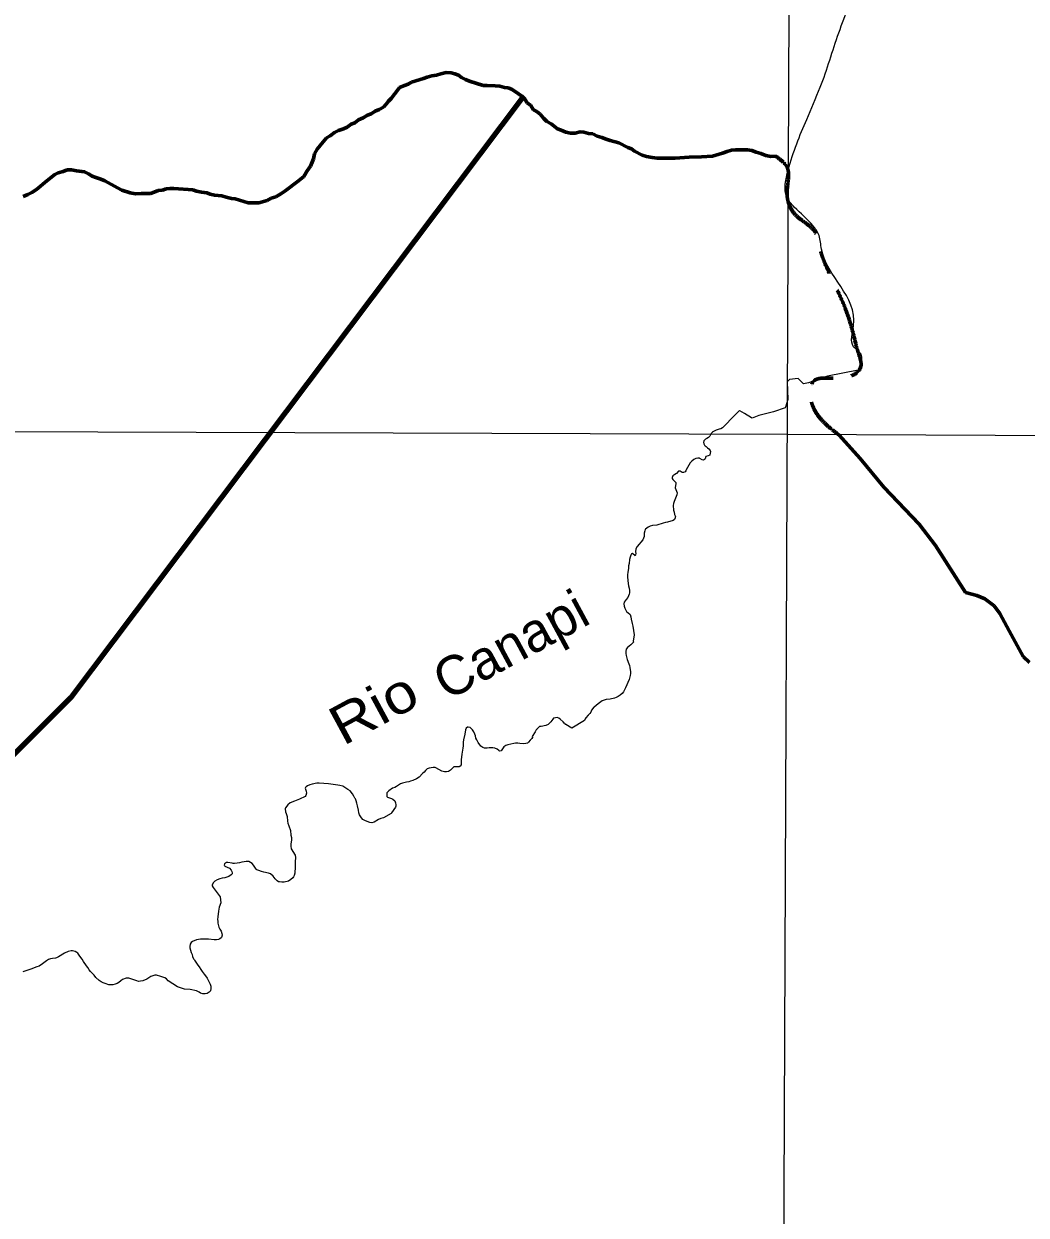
# Model space of a CAD drawing. Extents: x 553962 to 842807, y 8883888 to 9032388.
# Drawn here: x 655119 to 667950, y 8994810 to 9010061 of the extents above; entities that cross this region are included whole.
import ezdxf
from ezdxf.enums import TextEntityAlignment as Align

# ---------------------------------------------------------------- set-up
doc = ezdxf.new("R2010")
doc.units = 0
doc.header["$LTSCALE"] = 200
doc.linetypes.add('LONG_DASH_SHORT_DASH', pattern=[9.9, 6, -1.2, 1.5, -1.2])
for name, color, linetype, lineweight in [('1', 7, 'Continuous', 13), ('24', 7, 'Continuous', 25), ('7', 7, 'LONG_DASH_SHORT_DASH', 60), ('9', 7, 'Continuous', 90)]:
    doc.layers.add(name, color=color, linetype=linetype, lineweight=lineweight)
doc.layers.add('49', color=7, linetype='Continuous')

msp = doc.modelspace()

# ---------------------------------------------------------------- linework, layer by layer
at = {"layer": '1'}
for points in [[(664968.2, 9023436.8), (664657.1, 8949509), (664397.1, 8890880.2)], [(565303.2, 9005146.6), (664889.8, 9004806.7), (719872.1, 9004543.9), (790635.8, 9004109)]]:
    msp.add_lwpolyline(points, dxfattribs=at)
at = {"layer": '24'}
for points in [[(665798.1, 9005626.6), (665405.1, 9005550.8), (665165.6, 9005466.5), (665101.5, 9005450.6), (665032.2, 9005519.9), (664921.3, 9005506.1), (664888.7, 9005478.8)], [(664888.7, 9005478.8), (664900.1, 9005251.2), (664869.8, 9005153.3), (664865.4, 9005145.8), (664717.4, 9005095.4), (664528.5, 9005045), (664441.2, 9005012.7), (664432.8, 9005015.5), (664343.5, 9005072.6), (664286.2, 9005107.2), (664280.8, 9005109), (664271.5, 9005101.5), (664208.7, 9005038.3), (664080.1, 9004905.7)], [(664080.1, 9004905.7), (664063.5, 9004888.7), (664040.8, 9004876.6), (664021.9, 9004870), (663980.2, 9004861.2), (663946.3, 9004843.8), (663931.6, 9004832.2), (663929.7, 9004827.5), (663925.3, 9004825.6), (663922.8, 9004820.1), (663917.9, 9004815.5), (663910.5, 9004801.1), (663899, 9004783.8), (663883.9, 9004765), (663863.8, 9004751.9), (663845.5, 9004742.3), (663830.7, 9004729.4), (663824.8, 9004721.3), (663819.7, 9004702.6), (663823.3, 9004691.5), (663824.1, 9004683.3), (663832.8, 9004668.7), (663842.4, 9004656.8), (663854.1, 9004648.1), (663869.6, 9004633.8), (663887.6, 9004620.7), (663907, 9004598.9), (663907, 9004598.9), (663910.9, 9004584.5), (663902.4, 9004543.4), (663900.7, 9004539.3), (663881.2, 9004529), (663848.8, 9004520.2), (663839.5, 9004493.6), (663833.8, 9004483.1), (663820.7, 9004477), (663803.2, 9004478.8), (663774.4, 9004497.4), (663769.2, 9004499), (663746.7, 9004499.8), (663720.6, 9004496.7), (663695.8, 9004484.7), (663668.4, 9004461.3), (663648.1, 9004440.9), (663597.4, 9004352.2)], [(663597.4, 9004352.2), (663591.9, 9004338.7), (663585.2, 9004327.5), (663562, 9004318.3), (663545.8, 9004318.1), (663534.7, 9004324.6), (663525, 9004333.9), (663497.8, 9004335.9), (663473.3, 9004304.2), (663451.5, 9004291.8), (663425.3, 9004274.1), (663419.2, 9004251.7), (663419.6, 9004240.3), (663428.8, 9004227), (663461.2, 9004195.3), (663463.7, 9004190.3), (663466.9, 9004175.9), (663457.9, 9004121.1), (663483.9, 9004058.1), (663479.5, 9004030.4), (663444.7, 9003947.7), (663436.1, 9003919.8), (663430, 9003892.9), (663436.2, 9003836.4), (663444.6, 9003808.5), (663450.1, 9003780.8), (663459.3, 9003752.9), (663454.4, 9003726), (663450.1, 9003716.1), (663431.3, 9003702.2), (663360.9, 9003681.5), (663332.3, 9003676.8), (663305.3, 9003670.6), (663276.6, 9003659.9), (663248.8, 9003653.3), (663221, 9003644.9), (663165.3, 9003637.2), (663137.5, 9003629.7), (663109.8, 9003617.9), (663077.1, 9003593.6), (663073.8, 9003588.8), (663066.6, 9003572.2), (663061.7, 9003539.8), (663061.5, 9003511.9), (663059.4, 9003496.8), (663040.9, 9003457.1), (662971.2, 9003371.5), (662951.9, 9003338.4), (662948.3, 9003299.8), (662954, 9003282), (662947.1, 9003264.8), (662944, 9003251.6), (662942.9, 9003251.1), (662911.9, 9003278.6), (662899.6, 9003277.8), (662888.3, 9003260.5), (662879.6, 9003232.8), (662873.2, 9003204.9), (662866.8, 9003150.2), (662861.5, 9003121.4), (662858.9, 9003091.8), (662849.7, 9003038), (662846.5, 9003010.2), (662846.6, 9002979.2), (662855.1, 9002895.8), (662859.3, 9002866.8), (662868.7, 9002836.8), (662871.9, 9002808.7), (662871, 9002777.8), (662869.2, 9002761.2), (662849.1, 9002718.3), (662831.4, 9002691.2), (662805.1, 9002656.3), (662801.6, 9002634.7), (662804.8, 9002607.8), (662812, 9002578.7), (662832, 9002539.4), (662877.8, 9002502.9), (662881.5, 9002497.6), (662889.1, 9002470.7), (662893.7, 9002439.9), (662905.9, 9002382.7), (662915.2, 9002349), (662932.3, 9002238.2)], [(662932.3, 9002238.2), (662930.4, 9002232.8), (662918.7, 9002162.2), (662919.1, 9002158.4), (662924.3, 9002149.5), (662924.7, 9002146.9), (662910.5, 9002130.5), (662890.5, 9002112.2), (662844.9, 9002076.1), (662830.6, 9002055.4), (662824.1, 9002025.5), (662826.1, 9001999.9), (662830.2, 9001975), (662842.8, 9001924.6), (662865.6, 9001868.5), (662873.1, 9001845.7), (662878.6, 9001819.2), (662886, 9001766.9), (662885.8, 9001743), (662880.8, 9001718.2), (662866.3, 9001665.2), (662823, 9001561.5), (662795.5, 9001511.2), (662776.8, 9001488.3), (662751.1, 9001464.8), (662727, 9001447.9), (662703, 9001435.9), (662679.1, 9001427.9), (662625.9, 9001415.6), (662573.7, 9001409.9), (662524, 9001394.2), (662471, 9001354.5)], [(662471, 9001354.5), (662418, 9001314.7), (662413.9, 9001313.1), (662387.4, 9001275.2), (662375.4, 9001250.8), (662363.1, 9001233.2), (662344.9, 9001211.6), (662312, 9001177.4), (662303.6, 9001164.2), (662297.6, 9001142.3), (662132.9, 9001044.6), (662055.9, 9001090.7), (662051.5, 9001092.1), (662048.6, 9001095.2), (662046.8, 9001099.7), (662037.3, 9001108.4), (662022.2, 9001125.4), (661983.8, 9001159.7), (661966.6, 9001172.4), (661944.8, 9001178.8), (661926.5, 9001177.5), (661909.8, 9001173.8), (661901.4, 9001170.2), (661890.7, 9001159.3), (661864.8, 9001124.2), (661848.9, 9001108.4), (661829.4, 9001092.8), (661799.7, 9001079.5), (661781.2, 9001073.3), (661761.2, 9001070.8), (661742.7, 9001066.8), (661725.3, 9001066.6), (661721.3, 9001065.5), (661706.2, 9001054.2), (661685.2, 9001030.2), (661683.4, 9001024.9), (661678.4, 9001021.4), (661666.2, 9000995.9)], [(661666.2, 9000995.9), (661666, 9000995.8), (661628.2, 9000939.1), (661629.1, 9000923.3), (661621.8, 9000911.6), (661602.7, 9000889), (661580.6, 9000865.8), (661565.2, 9000853.8), (661545, 9000847.3), (661519.3, 9000842.1), (661468.8, 9000846.1), (661442.2, 9000850.3), (661414.8, 9000850.2), (661390.9, 9000847.2), (661313.8, 9000829), (661288.2, 9000820.3), (661264.1, 9000805.4), (661227.5, 9000755.1), (661208, 9000751.3), (661198.2, 9000757.5), (661179.9, 9000776.4), (661150.3, 9000789.5), (661123.7, 9000793.6), (661075.9, 9000790.6), (661048.4, 9000786.4), (661015, 9000789.2), (660997, 9000798), (660969.6, 9000815.2), (660936.1, 9000861.2), (660916.9, 9000893.2), (660906.5, 9000918), (660902.7, 9000944.6), (660893.5, 9000969.5), (660880.3, 9000995.9), (660864.7, 9001020.9), (660846.7, 9001041.3), (660832.8, 9001051.1), (660807.4, 9001057.7), (660797.2, 9001057), (660783.2, 9001044), (660772.5, 9001021.6), (660765.5, 9000968.5), (660747.9, 9000894.1), (660744.4, 9000865.7), (660743.2, 9000816.2), (660736.9, 9000789.6), (660730.5, 9000739.1), (660724.1, 9000712.6), (660715.8, 9000638.2), (660717.6, 9000586.8), (660716.8, 9000576.4), (660703.4, 9000556.3), (660691.2, 9000550.9), (660651.6, 9000550.6), (660627.7, 9000547.6), (660617, 9000544), (660613.3, 9000541.4), (660580.1, 9000504.8), (660556, 9000490), (660529.6, 9000484.5), (660503.9, 9000484.7), (660470.1, 9000491.9), (660394.1, 9000535.8), (660385, 9000538.7), (660360.5, 9000540.9), (660309.2, 9000533.2), (660284.4, 9000522.9), (660273.5, 9000516.3)], [(660273.5, 9000516.3), (660260.7, 9000503.6), (660242.4, 9000482.3), (660221.6, 9000464.5), (660179.6, 9000416.4), (660146.5, 9000396.3), (660098.7, 9000374.4), (660070.2, 9000365.5), (660046.2, 9000355.7), (660017.1, 9000352.3), (659968.3, 9000340.1), (659941.1, 9000330.8), (659916.1, 9000316.3), (659891.5, 9000299.3), (659868.5, 9000285.3), (659840.5, 9000274.1), (659791.5, 9000243.5), (659791.5, 9000243.5), (659764.1, 9000216.7)], [(659764.1, 9000216.7), (659766.6, 9000170.3), (659768.2, 9000165.1), (659774.5, 9000160.6), (659826.5, 9000142.5), (659840.8, 9000136.1), (659866.7, 9000114.8), (659877.4, 9000088.4), (659881.6, 9000062.4), (659881.8, 9000044.3), (659878.7, 9000033.4), (659825.5, 8999960), (659819.5, 8999953.8), (659723.2, 8999895.5), (659688.5, 8999887.8), (659659.7, 8999873.4), (659605.7, 8999841.4), (659576.1, 8999832.9), (659549.3, 8999836.2), (659494.5, 8999857.3), (659459.2, 8999876.8), (659440.5, 8999897.3), (659416.9, 8999934), (659408.9, 8999962.1), (659405.4, 8999993), (659391.8, 9000051.2), (659380, 9000082), (659373.4, 9000111.9), (659363.4, 9000140), (659357.1, 9000148.2), (659344.6, 9000173.6), (659327.4, 9000201.8), (659297.2, 9000242.3), (659268.6, 9000258.6), (659204.1, 9000299.8), (659165.9, 9000310.6), (659139.1, 9000316.3), (659110, 9000320.5), (659049.2, 9000326.1), (659018.4, 9000330.3), (658960.2, 9000334.5), (658898.5, 9000340.9), (658868.6, 9000338.6), (658809.5, 9000327), (658781.4, 9000320), (658750.4, 9000304), (658731.6, 9000292.7), (658725, 9000283.2), (658721, 9000274), (658723.2, 9000264.3), (658735.2, 9000237.8), (658736.5, 9000212.6), (658728.3, 9000183.5), (658719.9, 9000170.5), (658646.8, 9000134.5), (658582.1, 9000107.9), (658527.1, 9000087.1), (658500.7, 9000063.1), (658466.8, 9000023.7), (658464.3, 9000011.6), (658467.1, 8999971.4), (658475.8, 8999953.7), (658488.4, 8999914.2), (658494.9, 8999855.1), (658500.1, 8999826), (658513.6, 8999793.3), (658531.7, 8999732.1), (658538.8, 8999675.3), (658544, 8999643.4), (658543.9, 8999614.5), (658535.6, 8999557.6), (658535.5, 8999531.6), (658542.9, 8999498.1), (658590.6, 8999417.1), (658596.3, 8999388.5), (658593.3, 8999333.7), (658594.3, 8999302.9), (658591.1, 8999245.1), (658587, 8999215.1), (658587.8, 8999186), (658581.9, 8999159.2), (658571.8, 8999140.2), (658561.5, 8999126.8), (658537.9, 8999105.5), (658506.5, 8999084.8), (658451.1, 8999073.9), (658421.2, 8999073.9), (658391.5, 8999076.1), (658380.9, 8999077.9), (658363.2, 8999087.9), (658334.8, 8999114.2), (658310.6, 8999148.7), (658278.5, 8999178.4), (658249.9, 8999187.4), (658191.8, 8999200), (658161.8, 8999208.5), (658129.2, 8999220.1), (658104, 8999230.8), (658091.6, 8999239.2), (658060.2, 8999290.2), (658040.3, 8999310.8)], [(658040.3, 8999310.8), (658040.3, 8999310.8), (658000, 8999337.8), (657966.4, 8999338.9), (657938.3, 8999334), (657908.4, 8999330.6), (657878.4, 8999322.2), (657850.3, 8999317.1), (657817.7, 8999313.6), (657800.3, 8999313.7), (657787.5, 8999316.9), (657729.5, 8999326.2), (657712.2, 8999324.4), (657688.6, 8999307.5), (657685.1, 8999292.1), (657687.3, 8999285.1), (657693, 8999275.8), (657753.2, 8999252.7), (657775, 8999226.5), (657782.3, 8999211.3), (657785.2, 8999193), (657784.6, 8999178.2), (657773.8, 8999165.3), (657744.9, 8999144), (657690.9, 8999127.6), (657660.1, 8999123), (657630.1, 8999116.6), (657595.5, 8999103.3), (657562.7, 8999084.1), (657548.4, 8999069.4), (657544.1, 8999063.3), (657530.6, 8999033.5), (657531.1, 8999026), (657541, 8999005.5), (657634.2, 8998884.3), (657639.8, 8998808), (657621.8, 8998753.6), (657615.4, 8998727.9), (657612.9, 8998701.4), (657601.6, 8998627.3), (657600.2, 8998596.8), (657601.2, 8998573), (657604.3, 8998548.1), (657616.1, 8998496.8), (657628.2, 8998469.8), (657644.2, 8998443.7), (657653.9, 8998417.1), (657657.6, 8998393.2), (657648.4, 8998365.3), (657644.6, 8998359), (657626.4, 8998346.5), (657609.5, 8998339.4), (657584.9, 8998335.4), (657557.6, 8998334.5), (657484.2, 8998341.6), (657456.7, 8998341.8), (657430.2, 8998343.8), (657405.3, 8998342.9), (657378.8, 8998343.7), (657329.2, 8998335.4), (657279.9, 8998312.1), (657261.7, 8998299.4), (657250.3, 8998279.6), (657242.8, 8998249.8), (657243.3, 8998231.8), (657260.7, 8998173.6), (657272.5, 8998147), (657279.3, 8998120.5), (657289.5, 8998090.3), (657298.5, 8998083.2), (657303.2, 8998074.5), (657330.3, 8998035.7), (657345, 8998010.8), (657364.6, 8997987.5), (657384, 8997954.4), (657403.7, 8997929), (657426.3, 8997895.3), (657445.7, 8997875.4), (657467.3, 8997843.1), (657480.4, 8997819), (657504, 8997765.2), (657512, 8997741.1), (657513.1, 8997712.8), (657507.4, 8997682.2), (657504.9, 8997678.3), (657489.8, 8997663.3), (657464.9, 8997646.8), (657439.6, 8997643), (657411, 8997643.7), (657379.6, 8997651.8), (657363.8, 8997663.7), (657331.7, 8997680.8), (657249.9, 8997700.5), (657175.3, 8997701)], [(657175.3, 8997701), (657175.1, 8997701), (657100.8, 8997730.4), (657087.9, 8997731.3), (656968.2, 8997810), (656946.1, 8997833.3), (656924.4, 8997848.9), (656898.9, 8997857.8), (656872.4, 8997864.6), (656819.7, 8997882.6), (656819.7, 8997882.6), (656795.3, 8997881.5), (656768.8, 8997874.8), (656744, 8997863.3), (656694.2, 8997832.3), (656641.2, 8997809), (656614.7, 8997804.5), (656588, 8997802.9), (656564.2, 8997808.9), (656487.1, 8997835.5), (656463.2, 8997842.5), (656437.6, 8997844), (656427.7, 8997843.1), (656383.6, 8997825.4), (656359.4, 8997809.3), (656333.6, 8997789), (656313.6, 8997776.8), (656288.8, 8997765.3), (656260.5, 8997757.4), (656235.8, 8997756.4), (656208.1, 8997758.4), (656158.8, 8997774.9), (656133.9, 8997785.3), (656107.5, 8997798.6), (656084.2, 8997812.2), (656040, 8997850.5), (656017.7, 8997880.1), (655973.3, 8997930.8), (655954.3, 8997950.2), (655940.7, 8997978.6), (655923.1, 8998001.5), (655883.5, 8998057.7), (655867.9, 8998085.6), (655850.3, 8998107.5), (655828.3, 8998139.1), (655810.7, 8998161.9), (655799.2, 8998173.1), (655776, 8998185.7), (655740.7, 8998194.2), (655726.6, 8998194.9), (655688, 8998185.3), (655639.5, 8998162), (655564, 8998115.9), (655536.1, 8998103), (655526.2, 8998099.9), (655484.5, 8998096.5), (655459.7, 8998090.2), (655434.8, 8998080.9), (655409, 8998064), (655359.2, 8998025.6), (655313.6, 8997999.2), (655285.5, 8997987.2), (655210, 8997959), (655183.6, 8997951.1), (655157.8, 8997940.5)], [(655157.8, 8997940.5), (655107.3, 8997923.6)]]:
    msp.add_lwpolyline(points, dxfattribs=at)
msp.add_spline([(665804.3, 9005643.1), (665835.9, 9005832.9), (665741, 9005927.8), (665741, 9006196.7), (665330, 9007177.5), (665298.4, 9007351.5), (665219.3, 9007478.1), (664982.2, 9007715.4), (664887.3, 9007841.9), (664903.2, 9008190), (665140.3, 9008838.5), (665314.2, 9009249.8), (665551.3, 9009945.9), (665693.6, 9010293.9), (665962.4, 9010752.7), (666088.8, 9010942.5), (666468.3, 9011179.8), (666547.3, 9011306.3), (666847.7, 9011844.2), (667100.6, 9012508.6), (667369.4, 9012714.2), (667733, 9012603.5)], degree=3, dxfattribs=at)
at = {"layer": '7'}
for points in [[(659209.3, 9008717), (659256.9, 9008739.8), (659309.5, 9008775.2), (659357.1, 9008795.4), (659404.7, 9008830.8), (659464.8, 9008856.2), (659519.9, 9008891.6), (659567.5, 9008909.3), (659615.1, 9008942.2), (659667.8, 9008962.5), (659725.4, 9008992.9), (659757.9, 9009030.7), (659787.8, 9009070.9), (659822.9, 9009106.2), (659865.3, 9009159.1), (659892.8, 9009199.4), (659930.3, 9009247.3), (659990.4, 9009270.1), (660038.1, 9009290.4), (660080.7, 9009313.2), (660236.1, 9009361.6), (660281.2, 9009379.3), (660341.4, 9009397.2), (660401.7, 9009402.5), (660459.3, 9009422.8), (660527.1, 9009438.2), (660589.8, 9009435.9), (660637.6, 9009421.1), (660685.4, 9009403.7), (660723.1, 9009373.8), (660773.5, 9009346.4), (660826.2, 9009326.5), (660997.2, 9009272.1), (661049.9, 9009272.3), (661152.8, 9009267.7), (661210.6, 9009263), (661270.9, 9009248.2), (661318.6, 9009243.4), (661363.9, 9009226), (661409.2, 9009193.6), (661452, 9009166.2), (661492.3, 9009133.7), (661532.6, 9009096.2), (661560.4, 9009051.2), (661608.2, 9009013.8), (661641.1, 9008966.2), (661691.4, 9008936.3), (661729.2, 9008903.9), (661774.6, 9008851.3), (661814.9, 9008811.4), (661867.8, 9008781.5), (661950.8, 9008716.6), (661998.6, 9008701.8), (662059, 9008674.4), (662116.8, 9008659.6), (662177, 9008659.9), (662242.2, 9008680.2), (662289.9, 9008675.4), (662347.7, 9008658.1), (662403, 9008653.3), (662458.3, 9008623.5), (662518.6, 9008606.2), (662574, 9008583.8), (662624.2, 9008566.5), (662734.8, 9008536.9), (662850.5, 9008479.7), (662898.3, 9008462.3), (662936.1, 9008432.3), (663034.2, 9008380.1), (663089.5, 9008362.8), (663162.3, 9008348), (663225.1, 9008343.3), (663290.4, 9008341.1), (663458.6, 9008341.8), (663636.8, 9008352.6), (663792.4, 9008358.3), (663932.9, 9008369), (664063.3, 9008404.7), (664121, 9008425.1), (664178.6, 9008442.9), (664231.3, 9008448.1), (664334.2, 9008448.6), (664384.5, 9008446.3), (664439.7, 9008439), (664492.5, 9008419.2), (664552.8, 9008401.9), (664615.7, 9008374.6), (664683.5, 9008364.8), (664748.7, 9008365.1)], [(655109.7, 9007852.8), (655172.4, 9007878.2), (655220, 9007903.5), (655282.6, 9007941.5), (655412.8, 9008052.5), (655515.4, 9008130.8), (655560.5, 9008153.6), (655623.2, 9008171.4), (655673.4, 9008191.7), (655731.1, 9008192), (655794, 9008179.7), (655897, 9008165.1), (655947.3, 9008142.7), (655995.1, 9008112.8), (656042.9, 9008093), (656105.8, 9008070.6), (656156.1, 9008050.8), (656319.6, 9007963.7), (656372.5, 9007931.2), (656480.6, 9007899.1), (656550.9, 9007886.9), (656621.2, 9007887.2), (656681.5, 9007890), (656741.8, 9007890.2), (656786.9, 9007908), (656839.6, 9007925.8), (656894.8, 9007931.1), (656939.9, 9007948.8), (656990.1, 9007951.6), (657040.3, 9007951.8), (657098.1, 9007949.5), (657221.2, 9007940.1), (657283.9, 9007937.8), (657331.7, 9007920.5), (657392, 9007908.2), (657459.9, 9007898.4), (657505.1, 9007881.1), (657557.9, 9007866.2), (657605.6, 9007861.4), (657655.9, 9007859.2), (657708.7, 9007841.8), (657776.5, 9007827.1), (657824.2, 9007822.2), (657990.2, 9007767.8), (658125.8, 9007768.4), (658236.1, 9007799), (658286.2, 9007829.3), (658346.4, 9007847.2), (658409, 9007885.1), (658461.6, 9007920.5), (658634.4, 9008049.3), (658702, 9008104.8), (658744.3, 9008180.3), (658786.8, 9008240.7), (658809.2, 9008288.5), (658826.6, 9008333.8), (658841.4, 9008396.6), (658876.3, 9008457), (658911.3, 9008504.8), (658993.8, 9008600.6), (659038.9, 9008628.4), (659096.5, 9008668.8), (659149.1, 9008696.6), (659209.3, 9008717)], [(665554.2, 9004795.8), (665826.3, 9004496), (666128.4, 9004129.5), (666582.2, 9003656.2), (666791.2, 9003384.4), (667173.5, 9002782.6), (667316.8, 9002742.9), (667422.9, 9002700.1), (667541.5, 9002608.8), (667614.9, 9002511.4), (667732.4, 9002291), (667913.5, 9001963.7), (667993.5, 9001885.6)]]:
    msp.add_lwpolyline(points, dxfattribs=at)
msp.add_spline([(664746.7, 9008367.1), (664889.8, 9008223.9), (664889.8, 9007865.9), (665018.7, 9007593.8), (665247.7, 9007393.2), (665290.6, 9007250), (665362.2, 9007020.9), (665634.2, 9006419.4), (665748.7, 9006047), (665806, 9005832.2), (665834.6, 9005674.7), (665634.2, 9005531.4), (665219.1, 9005474.2), (665190.4, 9005273.6), (665554.2, 9004795.8)], degree=3, dxfattribs=at)
at = {"layer": '9'}
msp.add_lwpolyline([(635350.7, 8977923.9), (636116.8, 8981777.4), (642228, 8989744.8), (647160.3, 8990514), (649828, 8995545.6), (655722.5, 9001435.5), (661506.7, 9009120.3)], dxfattribs=at)

# ---------------------------------------------------------------- texts
at = {"layer": '49'}
msp.add_text('Canapi', height=500, rotation=28.393, dxfattribs=at).set_placement((661469, 9001892.9), align=Align.CENTER)
at = {"layer": '49', "width": 1.15}
msp.add_text('Rio', height=500, rotation=28.393, dxfattribs=at).set_placement((659714, 9001085.8), align=Align.CENTER)

doc.saveas('drawing.dxf')
